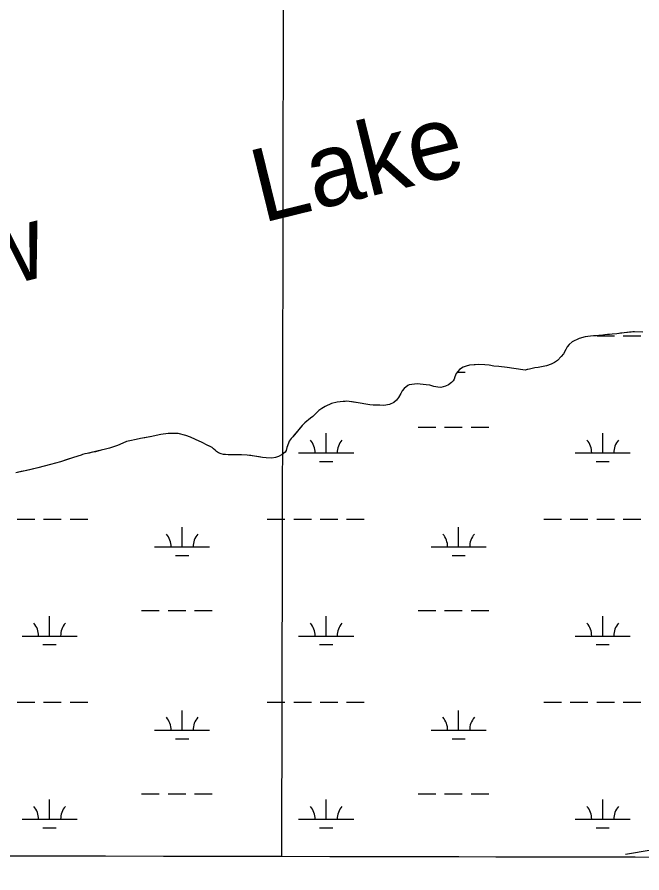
# Model space of a CAD drawing. Extents: x 3192927 to 3230760, y 831141 to 856475.
# Drawn here: x 3212321 to 3213455, y 836487 to 838041 of the extents above; entities that cross this region are included whole.
import ezdxf

# ---------------------------------------------------------------- set-up
doc = ezdxf.new("R2010")
doc.units = 0
for name, color, linetype in [('V-GRID-FRAM', 7, 'Continuous'), ('V-GRID-MAJR', 7, 'Continuous'), ('V-RIVR-IDEN', 7, 'Continuous'), ('V-ROAD-CNTR', 7, 'Continuous'), ('V-SITE-VEGE', 7, 'Continuous'), ('V-TOPO-SHOR', 7, 'Continuous'), ('V-WETL-SWMP', 7, 'Continuous')]:
    doc.layers.add(name, color=color, linetype=linetype)

msp = doc.modelspace()

# ---------------------------------------------------------------- linework, layer by layer
at = {"layer": 'V-GRID-FRAM'}
msp.add_lwpolyline([(3197144.3, 854733.3), (3228527.7, 854674), (3228501.2, 836486.7), (3197102, 836546.1), (3197144.3, 854733.3)], dxfattribs=at)
at = {"layer": 'V-GRID-MAJR'}
msp.add_spline([(3212801.6, 836516.4), (3212813.1, 842575.4), (3212824.5, 848637.8), (3212836, 854700.2), (3212836, 854703.6)], degree=3, dxfattribs=at)
at = {"layer": 'V-ROAD-CNTR'}
msp.add_lwpolyline([(3213619, 836552.8), (3213425.3, 836520.4)], dxfattribs=at)
at = {"layer": 'V-SITE-VEGE'}
for p, q in [((3213351.7, 837460.1), (3213341.3, 837456.9)), ((3213361.7, 837461.4), (3213351.7, 837460.1)), ((3213366.9, 837461.8), (3213361.7, 837461.4)), ((3213371.1, 837462), (3213366.9, 837461.8)), ((3213376.6, 837462.7), (3213371.1, 837462)), ((3213383.8, 837463.3), (3213376.6, 837462.7)), ((3213387.8, 837463.5), (3213383.8, 837463.3)), ((3213392.8, 837464.2), (3213387.8, 837463.5)), ((3213396.4, 837464.4), (3213392.8, 837464.2)), ((3213401, 837465), (3213396.4, 837464.4)), ((3213409.2, 837465.7), (3213401, 837465)), ((3213422.6, 837467.3), (3213409.2, 837465.7)), ((3213441.6, 837469.4), (3213422.6, 837467.3)), ((3213456.9, 837468.9), (3213441.6, 837469.4)), ((3213323, 837446.4), (3213319.6, 837442)), ((3213328.3, 837450.8), (3213323, 837446.4)), ((3213341.3, 837456.9), (3213328.3, 837450.8)), ((3213312.5, 837429.3), (3213308.7, 837424.3)), ((3213316.8, 837437.3), (3213312.5, 837429.3)), ((3213319.6, 837442), (3213316.8, 837437.3)), ((3213296.2, 837413.5), (3213290, 837410.4)), ((3213301.6, 837417.3), (3213296.2, 837413.5)), ((3213308.7, 837424.3), (3213301.6, 837417.3)), ((3213120.6, 837397.3), (3213118, 837393.6)), ((3213124, 837400.7), (3213120.6, 837397.3)), ((3213130.6, 837405.1), (3213124, 837400.7)), ((3213136.1, 837407.1), (3213130.6, 837405.1)), ((3213142.3, 837408.4), (3213136.1, 837407.1)), ((3213158.9, 837409.9), (3213142.3, 837408.4)), ((3213169.9, 837409.1), (3213158.9, 837409.9)), ((3213177.9, 837408.4), (3213169.9, 837409.1)), ((3213186.3, 837407), (3213177.9, 837408.4)), ((3213195.1, 837406.3), (3213186.3, 837407)), ((3213210.3, 837404.4), (3213195.1, 837406.3)), ((3213222.5, 837402.4), (3213210.3, 837404.4)), ((3213243.3, 837399.6), (3213222.5, 837402.4)), ((3213255.5, 837402.8), (3213243.3, 837399.6)), ((3213260.7, 837404.1), (3213255.5, 837402.8)), ((3213266.7, 837404.7), (3213260.7, 837404.1)), ((3213281.6, 837407.4), (3213266.7, 837404.7)), ((3213290, 837410.4), (3213281.6, 837407.4)), ((3213114.1, 837383.4), (3213112.5, 837380)), ((3213115.3, 837387.2), (3213114.1, 837383.4)), ((3213118, 837393.6), (3213115.3, 837387.2)), ((3213023.3, 837366.5), (3213020.1, 837362.1)), ((3213030, 837371.8), (3213023.3, 837366.5)), ((3213032.8, 837373), (3213030, 837371.8)), ((3213046.8, 837374.7), (3213032.8, 837373)), ((3213052.4, 837374.1), (3213046.8, 837374.7)), ((3213063.6, 837373.2), (3213052.4, 837374.1)), ((3213069.8, 837372.4), (3213063.6, 837373.2)), ((3213077.6, 837370.2), (3213069.8, 837372.4)), ((3213084.6, 837368.5), (3213077.6, 837370.2)), ((3213090, 837367.9), (3213084.6, 837368.5)), ((3213098.8, 837370.6), (3213090, 837367.9)), ((3213103.8, 837372.8), (3213098.8, 837370.6)), ((3213109.7, 837377), (3213103.8, 837372.8)), ((3213112.5, 837380), (3213109.7, 837377)), ((3213017.5, 837357.5), (3213013, 837350.1)), ((3213020.1, 837362.1), (3213017.5, 837357.5)), ((3212891.7, 837338.8), (3212880.1, 837333.5)), ((3212901.9, 837341.5), (3212891.7, 837338.8)), ((3212912.7, 837342.9), (3212901.9, 837341.5)), ((3212916.5, 837342.9), (3212912.7, 837342.9)), ((3212919.5, 837343.2), (3212916.5, 837342.9)), ((3212940.3, 837340.3), (3212919.5, 837343.2)), ((3212943.7, 837339.9), (3212940.3, 837340.3)), ((3212953.7, 837337.6), (3212943.7, 837339.9)), ((3212961.3, 837336.4), (3212953.7, 837337.6)), ((3212967.1, 837335.8), (3212961.3, 837336.4)), ((3212979.5, 837335.9), (3212967.1, 837335.8)), ((3212986.5, 837335.7), (3212979.5, 837335.9)), ((3212996.6, 837337), (3212986.5, 837335.7)), ((3213005, 837340.8), (3212996.6, 837337)), ((3213009.4, 837345.1), (3213005, 837340.8)), ((3213013, 837350.1), (3213009.4, 837345.1)), ((3212868.6, 837326.3), (3212857.5, 837315.6)), ((3212873.8, 837329.9), (3212868.6, 837326.3)), ((3212880.1, 837333.5), (3212873.8, 837329.9)), ((3212843.1, 837303.9), (3212838.6, 837299.1)), ((3212846.9, 837306.8), (3212843.1, 837303.9)), ((3212849.9, 837309.6), (3212846.9, 837306.8)), ((3212853.3, 837312.4), (3212849.9, 837309.6)), ((3212857.5, 837315.6), (3212853.3, 837312.4)), ((3212838.6, 837299.1), (3212821.3, 837278.8)), ((3212536.9, 837273.8), (3212525.8, 837271.4)), ((3212545.1, 837275.5), (3212536.9, 837273.8)), ((3212565.5, 837279.2), (3212545.1, 837275.5)), ((3212573.3, 837281), (3212565.5, 837279.2)), ((3212581.7, 837282.7), (3212573.3, 837281)), ((3212595.2, 837284.3), (3212581.7, 837282.7)), ((3212604, 837284.8), (3212595.2, 837284.3)), ((3212613.2, 837284.3), (3212604, 837284.8)), ((3212627.2, 837280.9), (3212613.2, 837284.3)), ((3212636, 837277.8), (3212627.2, 837280.9)), ((3212644.7, 837274), (3212636, 837277.8)), ((3212656.7, 837268.3), (3212644.7, 837274)), ((3212818.3, 837275.8), (3212815.1, 837270.6)), ((3212821.3, 837278.8), (3212818.3, 837275.8)), ((3212488.9, 837258), (3212481.5, 837256.1)), ((3212495.8, 837260.6), (3212488.9, 837258)), ((3212503, 837263), (3212495.8, 837260.6)), ((3212513, 837266.9), (3212503, 837263)), ((3212519.8, 837269.9), (3212513, 837266.9)), ((3212525.8, 837271.4), (3212519.8, 837269.9)), ((3212665.9, 837263.6), (3212656.7, 837268.3)), ((3212672.5, 837260.6), (3212665.9, 837263.6)), ((3212675.1, 837259), (3212672.5, 837260.6)), ((3212683, 837251.9), (3212675.1, 837259)), ((3212810.8, 837259.2), (3212809.1, 837253.8)), ((3212813.8, 837267.2), (3212810.8, 837259.2)), ((3212815.1, 837270.6), (3212813.8, 837267.2)), ((3212437.2, 837245.1), (3212423.2, 837241)), ((3212440, 837246.5), (3212437.2, 837245.1)), ((3212443.8, 837247.5), (3212440, 837246.5)), ((3212448.5, 837248.3), (3212443.8, 837247.5)), ((3212455.5, 837249.8), (3212448.5, 837248.3)), ((3212473.5, 837254.3), (3212455.5, 837249.8)), ((3212481.5, 837256.1), (3212473.5, 837254.3)), ((3212686.8, 837249.7), (3212683, 837251.9)), ((3212691.6, 837247.7), (3212686.8, 837249.7)), ((3212695.4, 837246.7), (3212691.6, 837247.7)), ((3212704.2, 837246), (3212695.4, 837246.7)), ((3212728.2, 837245.9), (3212704.2, 837246)), ((3212738.4, 837245.4), (3212728.2, 837245.9)), ((3212751.8, 837243.5), (3212738.4, 837245.4)), ((3212766.4, 837241.2), (3212751.8, 837243.5)), ((3212795.5, 837242.9), (3212789.9, 837240.9)), ((3212802.3, 837246.2), (3212795.5, 837242.9)), ((3212807.3, 837250.8), (3212802.3, 837246.2)), ((3212809.1, 837253.8), (3212807.3, 837250.8)), ((3212381.5, 837228.2), (3212359, 837222.2)), ((3212399.9, 837233.3), (3212381.5, 837228.2)), ((3212423.2, 837241), (3212399.9, 837233.3)), ((3212773.2, 837240.2), (3212766.4, 837241.2)), ((3212783.3, 837239.9), (3212773.2, 837240.2)), ((3212789.9, 837240.9), (3212783.3, 837239.9)), ((3212335.8, 837216.7), (3212318.6, 837213.4)), ((3212359, 837222.2), (3212335.8, 837216.7)), ((3211708, 836518.5), (3215770.2, 836510.8))]:
    msp.add_line(p, q, dxfattribs=at)
at = {"layer": 'V-TOPO-SHOR'}
for points in [[(3213456.9, 837468.9), (3213441.6, 837469.4), (3213438.2, 837469), (3213432.2, 837468.4), (3213422.6, 837467.3), (3213416, 837466.5), (3213409.2, 837465.7), (3213401, 837465), (3213396.4, 837464.4), (3213392.8, 837464.2), (3213387.8, 837463.5), (3213383.8, 837463.3), (3213376.6, 837462.7), (3213371.1, 837462), (3213366.9, 837461.8), (3213361.7, 837461.4), (3213351.7, 837460.1), (3213341.3, 837456.9), (3213328.3, 837450.8), (3213323, 837446.4), (3213319.6, 837442), (3213316.8, 837437.3), (3213312.5, 837429.3), (3213308.7, 837424.3), (3213301.6, 837417.3), (3213296.2, 837413.5), (3213290, 837410.4), (3213281.6, 837407.4), (3213266.7, 837404.7), (3213260.7, 837404.1), (3213255.5, 837402.8), (3213250.9, 837401.6), (3213246.9, 837400.6), (3213243.3, 837399.6), (3213222.5, 837402.4), (3213210.3, 837404.4), (3213195.1, 837406.3), (3213186.3, 837407), (3213177.9, 837408.4), (3213169.9, 837409.1), (3213158.9, 837409.9), (3213152.1, 837409.2), (3213142.3, 837408.4), (3213136.1, 837407.1), (3213130.6, 837405.1), (3213124, 837400.7), (3213120.6, 837397.3), (3213118, 837393.6), (3213115.3, 837387.2), (3213114.1, 837383.4), (3213112.5, 837380), (3213109.7, 837377), (3213103.8, 837372.8), (3213098.8, 837370.6), (3213090, 837367.9), (3213084.6, 837368.5), (3213077.6, 837370.2), (3213069.8, 837372.4), (3213063.6, 837373.2), (3213052.4, 837374.1), (3213046.8, 837374.7), (3213032.8, 837373), (3213030, 837371.8), (3213023.3, 837366.5), (3213020.1, 837362.1), (3213017.5, 837357.5), (3213013, 837350.1), (3213009.4, 837345.1), (3213005, 837340.8), (3212996.6, 837337), (3212986.5, 837335.7)], [(3212986.5, 837335.7), (3212979.5, 837335.9), (3212972.9, 837335.9), (3212967.1, 837335.8), (3212961.3, 837336.4), (3212953.7, 837337.6), (3212943.7, 837339.9), (3212940.3, 837340.3), (3212936.3, 837340.9), (3212929.3, 837341.8), (3212923.7, 837342.6), (3212919.5, 837343.2), (3212916.5, 837342.9), (3212912.7, 837342.9), (3212901.9, 837341.5), (3212891.7, 837338.8), (3212880.1, 837333.5), (3212873.8, 837329.9), (3212868.6, 837326.3), (3212862.6, 837320.6), (3212857.5, 837315.6), (3212853.3, 837312.4), (3212849.9, 837309.6), (3212846.9, 837306.8), (3212843.1, 837303.9), (3212838.6, 837299.1), (3212834.4, 837294.3), (3212830.4, 837289.5), (3212824.5, 837282.7), (3212821.3, 837278.8), (3212818.3, 837275.8), (3212815.1, 837270.6), (3212813.8, 837267.2), (3212812.6, 837264), (3212810.8, 837259.2), (3212809.1, 837253.8), (3212807.3, 837250.8), (3212802.3, 837246.2), (3212795.5, 837242.9), (3212789.9, 837240.9), (3212783.3, 837239.9), (3212773.2, 837240.2), (3212766.4, 837241.2), (3212760.4, 837242.1), (3212751.8, 837243.5), (3212745, 837244.4), (3212738.4, 837245.4), (3212728.2, 837245.9), (3212720.8, 837245.9), (3212710.4, 837246), (3212704.2, 837246), (3212699.4, 837246.4), (3212695.4, 837246.7), (3212691.6, 837247.7), (3212686.8, 837249.7), (3212683, 837251.9), (3212680.5, 837254.1), (3212677.5, 837256.8), (3212675.1, 837259), (3212672.5, 837260.6), (3212668.9, 837262.2), (3212665.9, 837263.6), (3212656.7, 837268.3), (3212644.7, 837274), (3212636, 837277.8), (3212627.2, 837280.9), (3212613.2, 837284.3), (3212604, 837284.8), (3212595.2, 837284.3), (3212581.7, 837282.7), (3212573.3, 837281), (3212565.5, 837279.2), (3212552.9, 837276.9), (3212545.1, 837275.5), (3212536.9, 837273.8), (3212525.8, 837271.4), (3212519.8, 837269.9), (3212513, 837266.9), (3212503, 837263), (3212495.8, 837260.6), (3212488.9, 837258), (3212481.5, 837256.1), (3212473.5, 837254.3), (3212463.1, 837251.6), (3212455.5, 837249.8), (3212451.7, 837249), (3212448.5, 837248.3), (3212443.8, 837247.5), (3212440, 837246.5), (3212437.2, 837245.1), (3212423.2, 837241), (3212412, 837237.3), (3212399.9, 837233.3), (3212381.5, 837228.2), (3212369.9, 837225.1), (3212359, 837222.2), (3212344.2, 837218.8), (3212335.8, 837216.7), (3212328.6, 837215.3), (3212318.6, 837213.4)]]:
    msp.add_lwpolyline(points, dxfattribs=at)
at = {"layer": 'V-WETL-SWMP'}
for p, q in [((3213351.7, 837460.1), (3213341.3, 837456.9)), ((3213361.7, 837461.4), (3213351.7, 837460.1)), ((3213366.9, 837461.8), (3213361.7, 837461.4)), ((3213371.1, 837462), (3213366.9, 837461.8)), ((3213376.6, 837462.7), (3213371.1, 837462)), ((3213373, 837462), (3213405, 837462)), ((3213383.8, 837463.3), (3213376.6, 837462.7)), ((3213387.8, 837463.5), (3213383.8, 837463.3)), ((3213392.8, 837464.2), (3213387.8, 837463.5)), ((3213396.4, 837464.4), (3213392.8, 837464.2)), ((3213401, 837465), (3213396.4, 837464.4)), ((3213409.2, 837465.7), (3213401, 837465)), ((3213416, 837466.5), (3213409.2, 837465.7)), ((3213422.6, 837467.3), (3213416, 837466.5)), ((3213421, 837462), (3213453, 837462)), ((3213432.2, 837468.4), (3213422.6, 837467.3)), ((3213438.2, 837469), (3213432.2, 837468.4)), ((3213441.6, 837469.4), (3213438.2, 837469)), ((3213456.9, 837468.9), (3213441.6, 837469.4)), ((3213323, 837446.4), (3213319.6, 837442)), ((3213328.3, 837450.8), (3213323, 837446.4)), ((3213341.3, 837456.9), (3213328.3, 837450.8)), ((3213312.5, 837429.3), (3213308.7, 837424.3)), ((3213316.8, 837437.4), (3213312.5, 837429.3)), ((3213319.6, 837442), (3213316.8, 837437.4)), ((3213296.2, 837413.5), (3213290, 837410.4)), ((3213301.6, 837417.3), (3213296.2, 837413.5)), ((3213308.7, 837424.3), (3213301.6, 837417.3)), ((3213120.6, 837397.3), (3213118, 837393.6)), ((3213124, 837400.7), (3213120.6, 837397.3)), ((3213130.6, 837405.1), (3213124, 837400.7)), ((3213136.1, 837407.1), (3213130.6, 837405.1)), ((3213142.3, 837408.4), (3213136.1, 837407.1)), ((3213152.1, 837409.2), (3213142.3, 837408.4)), ((3213158.9, 837409.9), (3213152.1, 837409.2)), ((3213169.9, 837409.1), (3213158.9, 837409.9)), ((3213177.9, 837408.4), (3213169.9, 837409.1)), ((3213186.3, 837407), (3213177.9, 837408.4)), ((3213195.1, 837406.3), (3213186.3, 837407)), ((3213210.3, 837404.4), (3213195.1, 837406.3)), ((3213222.5, 837402.4), (3213210.3, 837404.4)), ((3213243.3, 837399.6), (3213222.5, 837402.4)), ((3213246.9, 837400.6), (3213243.3, 837399.6)), ((3213250.9, 837401.6), (3213246.9, 837400.6)), ((3213255.5, 837402.8), (3213250.9, 837401.6)), ((3213260.7, 837404.1), (3213255.5, 837402.8)), ((3213266.7, 837404.7), (3213260.7, 837404.1)), ((3213281.6, 837407.4), (3213266.7, 837404.7)), ((3213290, 837410.4), (3213281.6, 837407.4)), ((3213114.1, 837383.4), (3213112.5, 837380)), ((3213115.3, 837387.2), (3213114.1, 837383.4)), ((3213118, 837393.6), (3213115.3, 837387.2)), ((3213119.6, 837395.8), (3213134.4, 837395.8)), ((3213023.3, 837366.5), (3213020.1, 837362.1)), ((3213030, 837371.8), (3213023.3, 837366.5)), ((3213032.8, 837373), (3213030, 837371.8)), ((3213046.8, 837374.7), (3213032.8, 837373)), ((3213052.4, 837374.1), (3213046.8, 837374.7)), ((3213063.6, 837373.2), (3213052.4, 837374.1)), ((3213069.8, 837372.4), (3213063.6, 837373.2)), ((3213077.6, 837370.2), (3213069.8, 837372.4)), ((3213084.6, 837368.5), (3213077.6, 837370.2)), ((3213090, 837367.9), (3213084.6, 837368.5)), ((3213098.8, 837370.6), (3213090, 837367.9)), ((3213103.8, 837372.8), (3213098.8, 837370.6)), ((3213109.7, 837377), (3213103.8, 837372.8)), ((3213112.5, 837380), (3213109.7, 837377)), ((3213017.5, 837357.5), (3213013, 837350.1)), ((3213020.1, 837362.1), (3213017.5, 837357.5)), ((3212891.7, 837338.8), (3212880.1, 837333.5)), ((3212901.9, 837341.5), (3212891.7, 837338.8)), ((3212912.7, 837342.9), (3212901.9, 837341.5)), ((3212916.5, 837342.9), (3212912.7, 837342.9)), ((3212919.5, 837343.2), (3212916.5, 837342.9)), ((3212936.3, 837340.9), (3212919.5, 837343.2)), ((3212940.3, 837340.3), (3212936.3, 837340.9)), ((3212943.7, 837339.9), (3212940.3, 837340.3)), ((3212953.7, 837337.6), (3212943.7, 837339.9)), ((3212961.3, 837336.4), (3212953.7, 837337.6)), ((3212967.1, 837335.8), (3212961.3, 837336.4)), ((3212979.5, 837335.9), (3212967.1, 837335.8)), ((3212986.5, 837335.7), (3212979.5, 837335.9)), ((3212996.6, 837337), (3212986.5, 837335.7)), ((3213005, 837340.8), (3212996.6, 837337)), ((3213009.4, 837345.1), (3213005, 837340.8)), ((3213013, 837350.1), (3213009.4, 837345.1)), ((3212862.6, 837320.6), (3212857.5, 837315.6)), ((3212868.6, 837326.3), (3212862.6, 837320.6)), ((3212873.8, 837329.9), (3212868.6, 837326.3)), ((3212880.1, 837333.5), (3212873.8, 837329.9)), ((3212843.1, 837303.9), (3212838.6, 837299.1)), ((3212846.9, 837306.8), (3212843.1, 837303.9)), ((3212849.9, 837309.6), (3212846.9, 837306.8)), ((3212853.3, 837312.4), (3212849.9, 837309.6)), ((3212857.5, 837315.6), (3212853.3, 837312.4)), ((3212830.4, 837289.5), (3212824.5, 837282.7)), ((3212834.4, 837294.3), (3212830.4, 837289.5)), ((3212838.6, 837299.1), (3212834.4, 837294.3)), ((3213049, 837295.8), (3213081, 837295.8)), ((3213097, 837295.8), (3213129, 837295.8)), ((3213145, 837295.8), (3213177, 837295.8)), ((3212536.9, 837273.8), (3212525.8, 837271.4)), ((3212545.1, 837275.5), (3212536.9, 837273.8)), ((3212552.9, 837276.9), (3212545.1, 837275.5)), ((3212565.5, 837279.2), (3212552.9, 837276.9)), ((3212573.3, 837281), (3212565.5, 837279.2)), ((3212581.7, 837282.7), (3212573.3, 837281)), ((3212595.2, 837284.3), (3212581.7, 837282.7)), ((3212604, 837284.8), (3212595.2, 837284.3)), ((3212613.2, 837284.3), (3212604, 837284.8)), ((3212627.2, 837280.9), (3212613.2, 837284.3)), ((3212636, 837277.8), (3212627.2, 837280.9)), ((3212644.7, 837274), (3212636, 837277.8)), ((3212656.7, 837268.3), (3212644.7, 837274)), ((3212818.3, 837275.8), (3212815.1, 837270.6)), ((3212821.3, 837278.8), (3212818.3, 837275.8)), ((3212824.5, 837282.7), (3212821.3, 837278.8)), ((3212881.9, 837249.4), (3212881.9, 837285.4)), ((3213383.8, 837249.4), (3213383.8, 837285.4)), ((3212488.9, 837258), (3212481.5, 837256.1)), ((3212495.8, 837260.6), (3212488.9, 837258)), ((3212503, 837263), (3212495.8, 837260.6)), ((3212513, 837266.9), (3212503, 837263)), ((3212519.8, 837269.9), (3212513, 837266.9)), ((3212525.8, 837271.4), (3212519.8, 837269.9)), ((3212665.9, 837263.6), (3212656.7, 837268.3)), ((3212668.9, 837262.2), (3212665.9, 837263.6)), ((3212672.5, 837260.6), (3212668.9, 837262.2)), ((3212675.1, 837259), (3212672.5, 837260.6)), ((3212677.5, 837256.8), (3212675.1, 837259)), ((3212810.8, 837259.2), (3212809.1, 837253.8)), ((3212813.8, 837267.2), (3212810.8, 837259.2)), ((3212815.1, 837270.6), (3212813.8, 837267.2)), ((3212437.2, 837245.1), (3212423.2, 837241)), ((3212440, 837246.5), (3212437.2, 837245.1)), ((3212443.8, 837247.5), (3212440, 837246.5)), ((3212448.5, 837248.3), (3212443.8, 837247.5)), ((3212451.7, 837249), (3212448.5, 837248.3)), ((3212455.5, 837249.8), (3212451.7, 837249)), ((3212463.1, 837251.6), (3212455.5, 837249.8)), ((3212473.5, 837254.3), (3212463.1, 837251.6)), ((3212481.5, 837256.1), (3212473.5, 837254.3)), ((3212680.5, 837254.1), (3212677.5, 837256.8)), ((3212683, 837251.9), (3212680.5, 837254.1)), ((3212686.8, 837249.7), (3212683, 837251.9)), ((3212691.6, 837247.7), (3212686.8, 837249.7)), ((3212695.4, 837246.7), (3212691.6, 837247.7)), ((3212699.4, 837246.4), (3212695.4, 837246.7)), ((3212704.2, 837246), (3212699.4, 837246.4)), ((3212710.4, 837246), (3212704.2, 837246)), ((3212720.8, 837245.9), (3212710.4, 837246)), ((3212728.2, 837245.9), (3212720.8, 837245.9)), ((3212738.4, 837245.4), (3212728.2, 837245.9)), ((3212745, 837244.4), (3212738.4, 837245.4)), ((3212751.8, 837243.5), (3212745, 837244.4)), ((3212760.4, 837242.1), (3212751.8, 837243.5)), ((3212766.4, 837241.2), (3212760.4, 837242.1)), ((3212795.5, 837242.9), (3212789.9, 837240.9)), ((3212802.3, 837246.2), (3212795.5, 837242.9)), ((3212807.3, 837250.8), (3212802.3, 837246.2)), ((3212809.1, 837253.8), (3212807.3, 837250.8)), ((3212831.9, 837249.4), (3212931.9, 837249.4)), ((3213333.8, 837249.4), (3213433.8, 837249.4)), ((3212381.5, 837228.2), (3212369.9, 837225.1)), ((3212399.9, 837233.3), (3212381.5, 837228.2)), ((3212412, 837237.3), (3212399.9, 837233.3)), ((3212423.2, 837241), (3212412, 837237.3)), ((3212773.2, 837240.2), (3212766.4, 837241.2)), ((3212783.3, 837239.9), (3212773.2, 837240.2)), ((3212789.9, 837240.9), (3212783.3, 837239.9)), ((3212869.9, 837233.9), (3212893.9, 837233.9)), ((3213371.8, 837233.9), (3213395.8, 837233.9)), ((3212328.6, 837215.3), (3212318.6, 837213.4)), ((3212335.8, 837216.7), (3212328.6, 837215.3)), ((3212344.2, 837218.8), (3212335.8, 837216.7)), ((3212359, 837222.2), (3212344.2, 837218.8)), ((3212369.9, 837225.1), (3212359, 837222.2)), ((3212321.2, 837129.3), (3212353.2, 837129.3)), ((3212369.2, 837129.3), (3212401.2, 837129.3)), ((3212417.2, 837129.3), (3212449.2, 837129.3)), ((3212775.1, 837129.3), (3212807.1, 837129.3)), ((3212823.1, 837129.3), (3212855.1, 837129.3)), ((3212871.1, 837129.3), (3212903.1, 837129.3)), ((3212919.1, 837129.3), (3212951.1, 837129.3)), ((3213277, 837129.3), (3213309, 837129.3)), ((3213325, 837129.3), (3213357, 837129.3)), ((3213373, 837129.3), (3213405, 837129.3)), ((3213421, 837129.3), (3213453, 837129.3)), ((3212620.5, 837078.6), (3212620.5, 837114.6)), ((3213122.4, 837078.6), (3213122.4, 837114.6)), ((3212570.5, 837078.6), (3212670.5, 837078.6)), ((3213072.4, 837078.6), (3213172.4, 837078.6)), ((3212608.5, 837063.1), (3212632.5, 837063.1)), ((3213110.4, 837063.1), (3213134.4, 837063.1)), ((3212547.1, 836963.1), (3212579.1, 836963.1)), ((3212595.1, 836963.1), (3212627.1, 836963.1)), ((3212643.1, 836963.1), (3212675.1, 836963.1)), ((3213049, 836963.1), (3213081, 836963.1)), ((3213097, 836963.1), (3213129, 836963.1)), ((3213145, 836963.1), (3213177, 836963.1)), ((3212380, 836916.7), (3212380, 836952.7)), ((3212881.9, 836916.7), (3212881.9, 836952.7)), ((3213383.8, 836916.7), (3213383.8, 836952.7)), ((3212330, 836916.7), (3212430, 836916.7)), ((3212831.9, 836916.7), (3212931.9, 836916.7)), ((3213333.8, 836916.7), (3213433.8, 836916.7)), ((3212368, 836901.3), (3212392, 836901.3)), ((3212869.9, 836901.3), (3212893.9, 836901.3)), ((3213371.8, 836901.3), (3213395.8, 836901.3)), ((3212321.2, 836796.6), (3212353.2, 836796.6)), ((3212369.2, 836796.6), (3212401.2, 836796.6)), ((3212417.2, 836796.6), (3212449.2, 836796.6)), ((3212775.1, 836796.6), (3212807.1, 836796.6)), ((3212823.1, 836796.6), (3212855.1, 836796.6)), ((3212871.1, 836796.6), (3212903.1, 836796.6)), ((3212919.1, 836796.6), (3212951.1, 836796.6)), ((3213277, 836796.6), (3213309, 836796.6)), ((3213325, 836796.6), (3213357, 836796.6)), ((3213373, 836796.6), (3213405, 836796.6)), ((3213421, 836796.6), (3213453, 836796.6)), ((3212620.5, 836745.9), (3212620.5, 836781.9)), ((3213122.4, 836745.9), (3213122.4, 836781.9)), ((3212570.5, 836745.9), (3212670.5, 836745.9)), ((3213072.4, 836745.9), (3213172.4, 836745.9)), ((3212608.5, 836730.4), (3212632.5, 836730.4)), ((3213110.4, 836730.4), (3213134.4, 836730.4)), ((3212380, 836584), (3212380, 836620)), ((3212547.1, 836630.4), (3212579.1, 836630.4)), ((3212595.1, 836630.4), (3212627.1, 836630.4)), ((3212643.1, 836630.4), (3212675.1, 836630.4)), ((3212881.9, 836584), (3212881.9, 836620)), ((3213049, 836630.4), (3213081, 836630.4)), ((3213097, 836630.4), (3213129, 836630.4)), ((3213145, 836630.4), (3213177, 836630.4)), ((3213383.8, 836584), (3213383.8, 836620)), ((3212330, 836584), (3212430, 836584)), ((3212831.9, 836584), (3212931.9, 836584)), ((3213333.8, 836584), (3213433.8, 836584)), ((3212368, 836568.6), (3212392, 836568.6)), ((3212869.9, 836568.6), (3212893.9, 836568.6)), ((3213371.8, 836568.6), (3213395.8, 836568.6)), ((3211708, 836518.5), (3215720.4, 836510.9))]:
    msp.add_line(p, q, dxfattribs=at)
for centre, start, end in [((3212826.7, 837249.8), 359.2282, 40.7718), ((3212937.2, 837249.8), 139.2282, 180.7718), ((3213328.6, 837249.8), 359.2282, 40.7718), ((3213439.1, 837249.8), 139.2282, 180.7718), ((3212565.3, 837079), 359.2282, 40.7718), ((3212675.7, 837079), 139.2282, 180.7718), ((3213067.2, 837079), 359.2282, 40.7718), ((3213177.6, 837079), 139.2282, 180.7718), ((3212324.8, 836917.2), 359.2282, 40.7718), ((3212435.3, 836917.2), 139.2282, 180.7718), ((3212826.7, 836917.2), 359.2282, 40.7718), ((3212937.2, 836917.2), 139.2282, 180.7718), ((3213328.6, 836917.2), 359.2282, 40.7718), ((3213439.1, 836917.2), 139.2282, 180.7718), ((3212565.3, 836746.3), 359.2282, 40.7718), ((3212675.7, 836746.3), 139.2282, 180.7718), ((3213067.2, 836746.3), 359.2282, 40.7718), ((3213177.6, 836746.3), 139.2282, 180.7718), ((3212324.8, 836584.5), 359.2282, 40.7718), ((3212435.3, 836584.5), 139.2282, 180.7718), ((3212826.7, 836584.5), 359.2282, 40.7718), ((3212937.2, 836584.5), 139.2282, 180.7718), ((3213328.6, 836584.5), 359.2282, 40.7718), ((3213439.1, 836584.5), 139.2282, 180.7718)]:
    msp.add_arc(centre, 35.2, start, end, dxfattribs=at)

# ---------------------------------------------------------------- texts
at = {"layer": 'V-RIVR-IDEN'}
msp.add_text('Shaw        Lake', height=133, rotation=13.8093, dxfattribs=at).set_placement((3211950, 837466.2))

doc.saveas('drawing.dxf')
